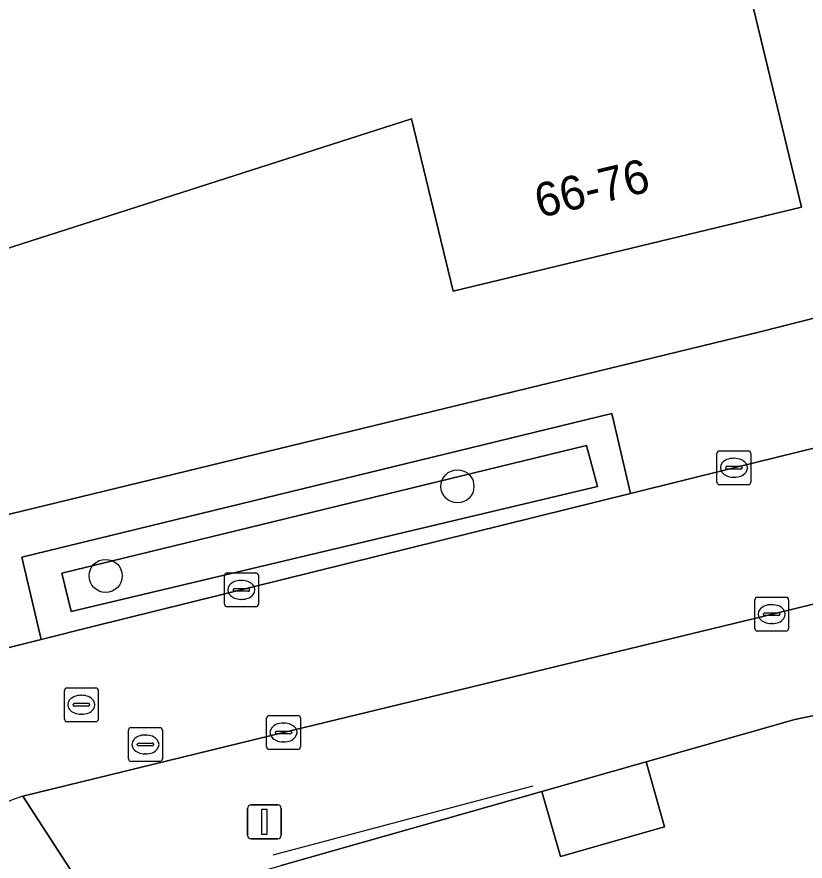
# Model space of a CAD drawing. Extents: x 159716 to 160783, y 383290 to 384031.
# Drawn here: x 160183.49 to 160206.79, y 383555.72 to 383580.67 of the extents above; entities that cross this region are included whole.
import ezdxf

# ---------------------------------------------------------------- set-up
doc = ezdxf.new("R2010")
doc.units = 0
for name, color, linetype in [('IMGEO_Boom', 7, 'Continuous'), ('IMGEO_Erf', 7, 'Continuous'), ('IMGEO_Groenvoorziening', 7, 'Continuous'), ('IMGEO_Kolk', 7, 'Continuous'), ('IMGEO_Lichtmast', 7, 'Continuous'), ('IMGEO_Muur', 7, 'Continuous'), ('IMGEO_Pand', 7, 'Continuous'), ('IMGEO_Pand_nummerreeks', 7, 'Continuous'), ('IMGEO_Rijbaan_lokaal_open', 7, 'Continuous'), ('IMGEO_Rioolput', 7, 'Continuous'), ('IMGEO_Voetpad_open', 7, 'Continuous')]:
    doc.layers.add(name, color=color, linetype=linetype)

msp = doc.modelspace()

# ---------------------------------------------------------------- linework, layer by layer
at = {"layer": 'IMGEO_Boom'}
for centre in [(160196.509, 383566.794), (160186.11, 383564.149)]:
    msp.add_circle(centre, 0.489, dxfattribs=at)
at = {"layer": 'IMGEO_Erf'}
for points in [[(160170.858, 383596.802), (160177.031, 383577.927), (160180.862, 383565.396), (160205.458, 383571.364), (160210.886, 383572.735), (160210.673, 383573.568), (160248.382, 383582.689)], [(160207.569, 383560.131), (160206.481, 383559.908), (160202.083, 383558.655), (160202.631, 383556.731), (160199.554, 383555.855), (160199.006, 383557.778), (160191.298, 383555.589)]]:
    msp.add_lwpolyline(points, dxfattribs=at)
msp.add_lwpolyline([(160203.838, 383586.788), (160206.676, 383575.044), (160196.384, 383572.56), (160195.153, 383577.656), (160179.168, 383572.534), (160172.879, 383592.192), (160184.301, 383595.87), (160188.402, 383583.057)], close=True, dxfattribs=at)
at = {"layer": 'IMGEO_Groenvoorziening'}
for points in [[(160201.073, 383568.946), (160183.632, 383564.707), (160184.208, 383562.271), (160185.732, 383562.649), (160201.624, 383566.584)], [(160185.093, 383563.101), (160184.816, 383564.228), (160200.32, 383568.003), (160200.647, 383566.794)], [(160185.093, 383563.101), (160200.647, 383566.794), (160200.32, 383568.003), (160184.816, 383564.228)]]:
    msp.add_lwpolyline(points, close=True, dxfattribs=at)
at = {"layer": 'IMGEO_Kolk'}
for p, q in [((160204.18, 383566.917), (160204.18, 383567.769)), ((160204.255, 383567.843), (160205.107, 383567.843)), ((160205.181, 383567.769), (160205.181, 383566.917)), ((160204.668, 383567.623), (160204.693, 383567.623)), ((160204.439, 383567.337), (160204.439, 383567.349)), ((160204.877, 383567.3), (160204.479, 383567.3)), ((160204.482, 383567.386), (160204.88, 383567.386)), ((160204.923, 383567.349), (160204.923, 383567.337)), ((160204.691, 383567.063), (160204.666, 383567.063)), ((160205.107, 383566.843), (160204.255, 383566.843)), ((160189.697, 383564.236), (160190.549, 383564.236)), ((160189.622, 383563.31), (160189.622, 383564.162)), ((160190.11, 383564.016), (160190.135, 383564.016)), ((160190.623, 383564.162), (160190.623, 383563.31)), ((160189.881, 383563.73), (160189.881, 383563.742)), ((160189.924, 383563.779), (160190.322, 383563.779)), ((160190.365, 383563.742), (160190.365, 383563.73)), ((160190.319, 383563.693), (160189.921, 383563.693)), ((160205.373, 383563.519), (160206.225, 383563.519)), ((160190.549, 383563.236), (160189.697, 383563.236)), ((160190.133, 383563.456), (160190.108, 383563.456)), ((160205.298, 383562.593), (160205.298, 383563.445)), ((160205.786, 383563.299), (160205.811, 383563.299)), ((160206.299, 383563.445), (160206.299, 383562.593)), ((160205.557, 383563.013), (160205.557, 383563.025)), ((160205.995, 383562.976), (160205.597, 383562.976)), ((160205.6, 383563.062), (160205.998, 383563.062)), ((160206.041, 383563.025), (160206.041, 383563.013)), ((160205.809, 383562.739), (160205.784, 383562.739)), ((160206.225, 383562.519), (160205.373, 383562.519)), ((160190.942, 383560.022), (160191.794, 383560.022)), ((160190.867, 383559.096), (160190.867, 383559.948)), ((160191.355, 383559.802), (160191.38, 383559.802)), ((160191.868, 383559.948), (160191.868, 383559.096)), ((160191.126, 383559.516), (160191.126, 383559.528)), ((160191.564, 383559.479), (160191.166, 383559.479)), ((160191.169, 383559.565), (160191.567, 383559.565)), ((160191.61, 383559.528), (160191.61, 383559.516)), ((160191.378, 383559.242), (160191.353, 383559.242)), ((160191.794, 383559.022), (160190.942, 383559.022))]:
    msp.add_line(p, q, dxfattribs=at)
for points in [[(160204.18, 383566.917), (160204.18, 383567.769)], [(160204.255, 383567.843), (160205.107, 383567.843)], [(160205.181, 383567.769), (160205.181, 383566.917)], [(160205.107, 383566.843), (160204.255, 383566.843)], [(160189.697, 383564.236), (160190.549, 383564.236)], [(160189.622, 383563.31), (160189.622, 383564.162)], [(160190.623, 383564.162), (160190.623, 383563.31)], [(160205.373, 383563.519), (160206.225, 383563.519)], [(160190.549, 383563.236), (160189.697, 383563.236)], [(160205.298, 383562.593), (160205.298, 383563.445)], [(160206.299, 383563.445), (160206.299, 383562.593)], [(160206.225, 383562.519), (160205.373, 383562.519)], [(160190.942, 383560.022), (160191.794, 383560.022)], [(160190.867, 383559.096), (160190.867, 383559.948)], [(160191.868, 383559.948), (160191.868, 383559.096)], [(160191.794, 383559.022), (160190.942, 383559.022)]]:
    msp.add_lwpolyline(points, dxfattribs=at)
for centre, radius, start, end in [((160204.257, 383567.767), 0.0765, 91.552, 178.448), ((160204.257, 383567.767), 0.0765, 91.552, 178.448), ((160205.105, 383567.767), 0.0765, 1.552, 88.448), ((160205.105, 383567.767), 0.0765, 1.552, 88.448), ((160204.479, 383567.346), 0.0403, 85.8775, 175.7526), ((160204.476, 383567.336), 0.0366, 178.938, 274.7102), ((160204.88, 383567.343), 0.043, 264.8664, 352.4533), ((160204.884, 383567.348), 0.0386, 1.7309, 96.639), ((160204.257, 383566.919), 0.0765, 181.552, 268.448), ((160204.257, 383566.919), 0.0765, 181.552, 268.448), ((160205.105, 383566.919), 0.0765, 271.552, 358.448), ((160205.105, 383566.919), 0.0765, 271.552, 358.448), ((160189.699, 383564.16), 0.0765, 91.552, 178.448), ((160189.699, 383564.16), 0.0765, 91.552, 178.448), ((160190.547, 383564.16), 0.0765, 1.552, 88.448), ((160190.547, 383564.16), 0.0765, 1.552, 88.448), ((160189.921, 383563.739), 0.0403, 85.8775, 175.7526), ((160189.918, 383563.729), 0.0366, 178.938, 274.7102), ((160190.322, 383563.736), 0.043, 264.8664, 352.4533), ((160190.326, 383563.741), 0.0386, 1.7309, 96.639), ((160205.375, 383563.443), 0.0765, 91.552, 178.448), ((160205.375, 383563.443), 0.0765, 91.552, 178.448), ((160206.223, 383563.443), 0.0765, 1.552, 88.448), ((160206.223, 383563.443), 0.0765, 1.552, 88.448), ((160189.699, 383563.312), 0.0765, 181.552, 268.448), ((160189.699, 383563.312), 0.0765, 181.552, 268.448), ((160190.547, 383563.312), 0.0765, 271.552, 358.448), ((160190.547, 383563.312), 0.0765, 271.552, 358.448), ((160205.597, 383563.022), 0.0403, 85.8775, 175.7526), ((160205.594, 383563.012), 0.0366, 178.938, 274.7102), ((160205.998, 383563.019), 0.043, 264.8664, 352.4533), ((160206.002, 383563.024), 0.0386, 1.7309, 96.639), ((160205.375, 383562.595), 0.0765, 181.552, 268.448), ((160205.375, 383562.595), 0.0765, 181.552, 268.448), ((160206.223, 383562.595), 0.0765, 271.552, 358.448), ((160206.223, 383562.595), 0.0765, 271.552, 358.448), ((160190.944, 383559.946), 0.0765, 91.552, 178.448), ((160190.944, 383559.946), 0.0765, 91.552, 178.448), ((160191.792, 383559.946), 0.0765, 1.552, 88.448), ((160191.792, 383559.946), 0.0765, 1.552, 88.448), ((160191.166, 383559.525), 0.0403, 85.8775, 175.7526), ((160191.163, 383559.515), 0.0366, 178.938, 274.7102), ((160191.567, 383559.522), 0.043, 264.8664, 352.4533), ((160191.571, 383559.527), 0.0386, 1.7309, 96.639), ((160190.944, 383559.098), 0.0765, 181.552, 268.448), ((160190.944, 383559.098), 0.0765, 181.552, 268.448), ((160191.792, 383559.098), 0.0765, 271.552, 358.448), ((160191.792, 383559.098), 0.0765, 271.552, 358.448)]:
    msp.add_arc(centre, radius, start, end, dxfattribs=at)
for centre, major_axis, ratio, start_param, end_param in [((160204.667, 383567.343), (-0.387, 0.002), 0.722429, 4.712389, 7.853982), ((160204.692, 383567.343), (-0.39, 0.002), 0.717154, 1.570796, 4.712389), ((160190.109, 383563.736), (-0.387, 0.002), 0.722429, 4.712389, 7.853982), ((160190.134, 383563.736), (-0.39, 0.002), 0.717154, 1.570796, 4.712389), ((160205.785, 383563.019), (-0.387, 0.002), 0.722429, 4.712389, 7.853982), ((160205.81, 383563.019), (-0.39, 0.002), 0.717154, 1.570796, 4.712389), ((160191.354, 383559.522), (-0.387, 0.002), 0.722429, 4.712389, 7.853982), ((160191.379, 383559.522), (-0.39, 0.002), 0.717154, 1.570796, 4.712389)]:
    msp.add_ellipse(centre, major_axis=major_axis, ratio=ratio, start_param=start_param, end_param=end_param, dxfattribs=at)
at = {"layer": 'IMGEO_Lichtmast'}
for p, q in [((160190.306, 383556.48), (160190.306, 383557.28)), ((160190.306, 383557.28), (160190.306, 383556.48)), ((160190.406, 383557.38), (160191.196, 383557.38)), ((160191.196, 383557.38), (160190.406, 383557.38)), ((160191.296, 383557.28), (160191.296, 383556.48)), ((160191.296, 383556.48), (160191.296, 383557.28)), ((160191.196, 383556.38), (160190.406, 383556.38)), ((160190.406, 383556.38), (160191.196, 383556.38))]:
    msp.add_line(p, q, dxfattribs=at)
msp.add_lwpolyline([(160190.726, 383557.255), (160190.876, 383557.255), (160190.876, 383556.505), (160190.726, 383556.505), (160190.726, 383557.255)], dxfattribs=at)
for centre, start, end in [((160190.406, 383557.28), 90, 180), ((160190.406, 383557.28), 90, 180), ((160191.196, 383557.28), 0, 90), ((160191.196, 383557.28), 360, 90), ((160190.406, 383556.48), 180, 270), ((160190.406, 383556.48), 180, 270), ((160191.196, 383556.48), 270, 0), ((160191.196, 383556.48), 270, 0)]:
    msp.add_arc(centre, 0.1, start, end, dxfattribs=at)
at = {"layer": 'IMGEO_Muur'}
msp.add_lwpolyline([(160191.063, 383555.903), (160198.746, 383557.95)], dxfattribs=at)
at = {"layer": 'IMGEO_Pand'}
for points in [[(160203.838, 383586.788), (160188.402, 383583.057), (160184.301, 383595.87), (160172.879, 383592.192), (160179.168, 383572.534), (160195.153, 383577.656), (160196.384, 383572.56), (160206.676, 383575.044)], [(160202.083, 383558.655), (160199.006, 383557.778), (160199.554, 383555.855), (160202.631, 383556.731)]]:
    msp.add_lwpolyline(points, close=True, dxfattribs=at)
at = {"layer": 'IMGEO_Rijbaan_lokaal_open'}
for points in [[(160248.382, 383582.689), (160210.673, 383573.568), (160210.886, 383572.735), (160205.458, 383571.364), (160180.862, 383565.396), (160176.038, 383563.423)], [(160205.902, 383563.034), (160207.107, 383563.332), (160215.31, 383565.33), (160216.362, 383565.576), (160231.611, 383569.287), (160230.557, 383573.643), (160218.131, 383570.622), (160215.675, 383570.025), (160210.926, 383568.88), (160204.681, 383567.343), (160201.624, 383566.584), (160185.732, 383562.649), (160184.208, 383562.271), (160181.857, 383561.686)], [(160181.857, 383561.686), (160184.208, 383562.271), (160183.632, 383564.707), (160201.073, 383568.946), (160201.624, 383566.584), (160204.681, 383567.343), (160210.926, 383568.88), (160210.627, 383570.094), (160212.021, 383570.42), (160215.388, 383571.208), (160215.17, 383572.106), (160217.858, 383572.713), (160218.144, 383572.603)], [(160183.659, 383557.645), (160191.368, 383559.522), (160205.902, 383563.034)]]:
    msp.add_lwpolyline(points, dxfattribs=at)
msp.add_arc((160185.761, 383551.584), 6.415, 109.1249, 192.5443, dxfattribs=at)
at = {"layer": 'IMGEO_Rioolput'}
for p, q in [((160184.892, 383559.915), (160184.892, 383560.767)), ((160184.967, 383560.841), (160185.819, 383560.841)), ((160185.893, 383560.767), (160185.893, 383559.915)), ((160185.38, 383560.621), (160185.405, 383560.621)), ((160185.151, 383560.335), (160185.151, 383560.347)), ((160185.589, 383560.298), (160185.191, 383560.298)), ((160185.194, 383560.384), (160185.592, 383560.384)), ((160185.635, 383560.347), (160185.635, 383560.335)), ((160185.403, 383560.061), (160185.378, 383560.061)), ((160185.819, 383559.841), (160184.967, 383559.841)), ((160186.786, 383558.742), (160186.786, 383559.594)), ((160186.861, 383559.668), (160187.713, 383559.668)), ((160187.787, 383559.594), (160187.787, 383558.742)), ((160187.274, 383559.448), (160187.299, 383559.448)), ((160187.045, 383559.162), (160187.045, 383559.174)), ((160187.483, 383559.125), (160187.085, 383559.125)), ((160187.088, 383559.211), (160187.486, 383559.211)), ((160187.529, 383559.174), (160187.529, 383559.162)), ((160187.297, 383558.888), (160187.272, 383558.888)), ((160187.713, 383558.668), (160186.861, 383558.668))]:
    msp.add_line(p, q, dxfattribs=at)
for points in [[(160184.892, 383559.915), (160184.892, 383560.767)], [(160184.967, 383560.841), (160185.819, 383560.841)], [(160185.893, 383560.767), (160185.893, 383559.915)], [(160185.819, 383559.841), (160184.967, 383559.841)], [(160186.786, 383558.742), (160186.786, 383559.594)], [(160186.861, 383559.668), (160187.713, 383559.668)], [(160187.787, 383559.594), (160187.787, 383558.742)], [(160187.713, 383558.668), (160186.861, 383558.668)]]:
    msp.add_lwpolyline(points, dxfattribs=at)
for centre, radius, start, end in [((160184.969, 383560.765), 0.0765, 91.552, 178.448), ((160184.969, 383560.765), 0.0765, 91.552, 178.448), ((160185.817, 383560.765), 0.0765, 1.552, 88.448), ((160185.817, 383560.765), 0.0765, 1.552, 88.448), ((160185.191, 383560.344), 0.0403, 85.8775, 175.7526), ((160185.188, 383560.334), 0.0366, 178.938, 274.7102), ((160185.592, 383560.341), 0.043, 264.8664, 352.4533), ((160185.596, 383560.346), 0.0386, 1.7309, 96.639), ((160184.969, 383559.917), 0.0765, 181.552, 268.448), ((160184.969, 383559.917), 0.0765, 181.552, 268.448), ((160185.817, 383559.917), 0.0765, 271.552, 358.448), ((160185.817, 383559.917), 0.0765, 271.552, 358.448), ((160186.863, 383559.592), 0.0765, 91.552, 178.448), ((160186.863, 383559.592), 0.0765, 91.552, 178.448), ((160187.711, 383559.592), 0.0765, 1.552, 88.448), ((160187.711, 383559.592), 0.0765, 1.552, 88.448), ((160187.085, 383559.171), 0.0403, 85.8775, 175.7526), ((160187.082, 383559.161), 0.0366, 178.938, 274.7102), ((160187.486, 383559.168), 0.043, 264.8664, 352.4533), ((160187.49, 383559.173), 0.0386, 1.7309, 96.639), ((160186.863, 383558.744), 0.0765, 181.552, 268.448), ((160186.863, 383558.744), 0.0765, 181.552, 268.448), ((160187.711, 383558.744), 0.0765, 271.552, 358.448), ((160187.711, 383558.744), 0.0765, 271.552, 358.448)]:
    msp.add_arc(centre, radius, start, end, dxfattribs=at)
for centre, major_axis, ratio, start_param, end_param in [((160185.379, 383560.341), (-0.387, 0.002), 0.722429, 4.712389, 7.853982), ((160185.404, 383560.341), (-0.39, 0.002), 0.717154, 1.570796, 4.712389), ((160187.273, 383559.168), (-0.387, 0.002), 0.722429, 4.712389, 7.853982), ((160187.298, 383559.168), (-0.39, 0.002), 0.717154, 1.570796, 4.712389)]:
    msp.add_ellipse(centre, major_axis=major_axis, ratio=ratio, start_param=start_param, end_param=end_param, dxfattribs=at)
at = {"layer": 'IMGEO_Voetpad_open'}
for points in [[(160206.481, 383559.908), (160207.569, 383560.131), (160208.331, 383560.287), (160208.467, 383560.285), (160209.46, 383556.921), (160211.542, 383557.498), (160216.391, 383558.613), (160219.583, 383559.225), (160253.749, 383567.499), (160253.089, 383570.307), (160258.339, 383571.813), (160262.793, 383573.1), (160267.131, 383574.352), (160271.583, 383575.638), (160274.036, 383576.37), (160275.937, 383576.879), (160275.692, 383577.25)], [(160216.362, 383565.576), (160215.31, 383565.33), (160215.594, 383564.134), (160207.385, 383562.159), (160207.107, 383563.332), (160205.902, 383563.034), (160191.368, 383559.522), (160183.659, 383557.645), (160185.988, 383554.056), (160191.298, 383555.589), (160199.006, 383557.778), (160202.083, 383558.655), (160206.481, 383559.908)], [(160193.799, 383526.989), (160192.474, 383531.142), (160191.149, 383535.295), (160189.824, 383539.449), (160188.499, 383543.602), (160187.174, 383547.755), (160187.053, 383548.136), (160186.437, 383547.934), (160185.206, 383551.786), (160186.558, 383552.219), (160185.988, 383554.056), (160183.659, 383557.645)]]:
    msp.add_lwpolyline(points, dxfattribs=at)
msp.add_arc((160185.761, 383551.584), 6.415, 109.1249, 192.5443, dxfattribs=at)

# ---------------------------------------------------------------- texts
at = {"layer": 'IMGEO_Pand_nummerreeks'}
msp.add_text('66-76', height=1, rotation=13.5676, dxfattribs=at).set_placement((160198.934, 383574.719))

doc.saveas('drawing.dxf')
